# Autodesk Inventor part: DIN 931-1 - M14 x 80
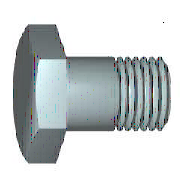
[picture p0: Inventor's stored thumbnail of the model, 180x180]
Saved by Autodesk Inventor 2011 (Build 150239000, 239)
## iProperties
Created: 2010-02
Part Number: DIN 931-1 - M14 x 80
Material: Steel, Mild
Description: Hex-Head Bolt
Document SubType Name: Modeling
Standard: DIN 931-1
Designer: PC
Standard Revision: 2001
Standards Organization: DIN
Language: en-US
Size Designation: M14 x 80
Categories: <MemberInstance><Categories><Category DisplayName="Fasteners" InternalName="e4da775c-781d-43d5-af7c-5136215cf5a6" Mnemonic="FSTN"><Category DisplayName="Bolts"
Density: 1 g/cm^3
IsCustomPart: 0
Author: PC
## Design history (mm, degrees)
workplane "Work Plane1"
revolve "Body" stored, may be unused: angle "d12" = 90 deg
sketch "Sketch2"
  geometry: L1 (0, 12.702)-(11, 6.351); L2 (11, 6.351)-(11, -6.351); L3 (11, -6.351)-(0, -12.702); L4 (0, -12.702)-(-11, -6.351); L5 (-11, -6.351)-(-11, 6.351); L6 (-11, 6.351)-(0, 12.702); 2 further points
  constraints: 12 end point, 1 coincident, 1 vertical, 11 other
  dimensions: "d11" = 22 distance between parallel lines of L5 L2 (= SW)
extrude "Head" join sketch "Sketch2" distance "d3" = 8.2 (= KOH - SD); taper "d4" = 0 deg
revolve "Chamfer1" stored, may be unused: angle "d21" = 90 deg
body "Solid1"
feature "Thread" dims "d15" = 34 (= GEL), "d16" = 0
chamfer "Chamfer2" distance "d6" = 1.2269 (= -0.5 x SPD + 0.5 x GD); stored, may be unused: second distance "d7" = 1.227 (computed from GUL), angle "d55" = 45 deg
sketch "Sketch1"
  geometry: L1 (0, 10.25)-(0, 7); L2 (46, 7)-(80, 7); L3 (80, 7)-(80, 0); L4 (80, 0)-(-0.6, 0); L5 (-16.72, 0)-(96.12, 0) reference; L6 (-0.6, 0)-(-0.6, 10.25); L7 (-0.6, 10.25)-(0, 10.25); L8 (46, 7)-(44.773, 7); L9 (44.773, 7)-(0, 7); L10 (0, -2.05)-(0, 12.3) reference
  constraints: 16 end point, 2 collinear, 2 perpendicular, 1 parallel
  dimensions: "d0" = 80 distance between parallel lines of L3 L1 (= NLG); "d1" = 34 distance from line of L2.start L3 (= GEL); "d2" = 14 diameter of L2 L4 (= GD); "d9" = 0.6001 distance between parallel lines of L6 L1 (computed from SD); "d10" = 20.5 diameter of L7 L4 (= SD2); "d13" = 1.227 distance of L2.start L8.end (computed from GAL); "d14" = 14 diameter of L9 L4 (= BDM)
sketch "Sketch4"
  geometry: L1 (-8.8, 11)-(-8.8, 12.702); L2 (-8.8, 12.702)-(-7.818, 12.702); L3 (-7.818, 12.702)-(-8.8, 11); L4 (-10.44, 0)-(1.04, 0) reference; L5 (-0.6, 12.702)-(-8.8, 12.702) reference; L6 (-8.8, 6.351)-(-8.8, 12.702) reference
  constraints: 6 end point, 2 collinear, 1 perpendicular, 1 vertical
  dimensions: "d5" = 30 deg angle of L3 L1 (= ANG1); "d19" = 22 diameter of L1.start L4 (= SW0)
other parameters: "NLG" = 80 [user parameter; used in 1 equation term], "GD" = 14 (= NND) [user parameter; used in 2 equation terms], "BDM" = 14 (= NND) [user parameter; used in 1 equation term], "KOH" = 8.8 [user parameter; used in 1 equation term], "GEL" = 34 [user parameter; used in 2 equation terms], "SW" = 22 [user parameter; used in 3 equation terms], "SW0" = 22 (= SW) [user parameter; used in 1 equation term], "SPD" = 11.5462 (= NND - 1.2269 x PTC) [user parameter; used in 1 equation term], "SD2" = 20.5 [user parameter; used in 1 equation term], "SD" = 0.6 [user parameter; used in 2 equation terms], "ANG1" = 30 deg [user parameter; used in 1 equation term], "GAL" = 1.2269 (= 0.61345 x PTC) [user parameter; used in 1 equation term], "GUL" = 1.2269 (= 0.61345 x PTC) [user parameter; used in 1 equation term], "d8" = 0, "RR" = 0.6 [user parameter], "d57" = 0, "d58" = 0, "TPU" = 5 (computed from PTC) [user parameter], "GD1" = 11.5462 (= THREADDIA - 1.2269 x PTC) [user parameter], "THREADDIA" = 14 [user parameter; used in 1 equation term], "TOA" = 30 deg [user parameter], "PTC" = 2 [user parameter; used in 5 equation terms], "NND" = 14 [user parameter; used in 3 equation terms], "E0" = 25.41 (= 1.155 x SW) [user parameter]
